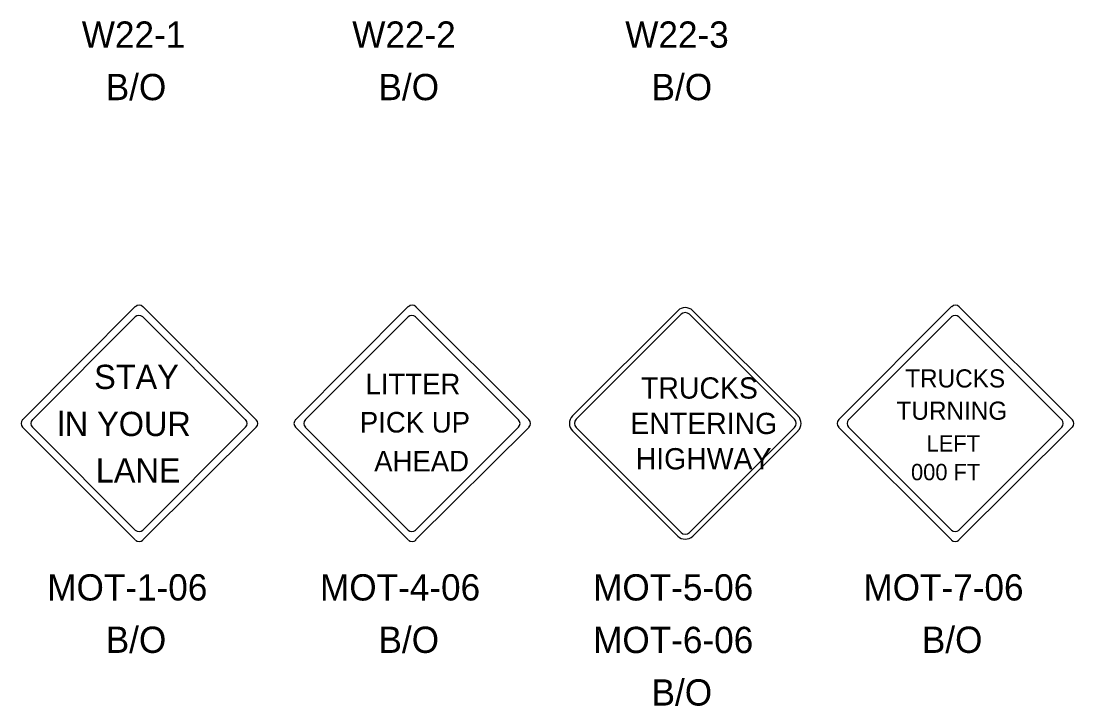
# Model space of a CAD drawing. Extents: x 10034 to 10794, y 10044 to 10499.
# Drawn here: x 10033.9 to 10174.1, y 10063.7 to 10155 of the extents above; entities that cross this region are included whole.
import ezdxf

# ---------------------------------------------------------------- set-up
doc = ezdxf.new("R2010")
doc.units = 0
for name, color, linetype in [('DSIndex', 7, 'Continuous'), ('DSSheetNo', 7, 'Continuous'), ('DSText', 7, 'Continuous'), ('DSTitle', 7, 'Continuous'), ('PlotBorder_dp', 7, 'Continuous')]:
    doc.layers.add(name, color=color, linetype=linetype)

msp = doc.modelspace()

# ---------------------------------------------------------------- linework, layer by layer
at = {"layer": 'DSSheetNo'}
for p, q in [((10049.13, 10116.94), (10034.1, 10101.87)), ((10065.24, 10101.87), (10050.12, 10116.94)), ((10085.48, 10116.94), (10070.46, 10101.87)), ((10101.59, 10101.87), (10086.47, 10116.94)), ((10157.83, 10116.94), (10142.81, 10101.87)), ((10173.94, 10101.87), (10158.82, 10116.94)), ((10034.1, 10100.87), (10049.13, 10085.85)), ((10050.12, 10085.85), (10065.23, 10100.86)), ((10070.46, 10100.87), (10085.48, 10085.85)), ((10086.47, 10085.85), (10101.59, 10100.87)), ((10142.81, 10100.87), (10157.83, 10085.85)), ((10158.82, 10085.85), (10173.93, 10100.86))]:
    msp.add_line(p, q, dxfattribs=at)
for centre, start, end in [((10049.66, 10116.41), 45, 135), ((10086.02, 10116.41), 45, 135), ((10158.37, 10116.41), 45, 135), ((10034.63, 10101.38), 135, 225), ((10064.74, 10101.37), 315, 45), ((10070.98, 10101.38), 135, 225), ((10101.05, 10101.38), 315, 45), ((10143.33, 10101.38), 135, 225), ((10173.44, 10101.37), 315, 45), ((10049.66, 10086.34), 225, 315), ((10086.02, 10086.34), 225, 315)]:
    msp.add_arc(centre, 0.709, start, end, dxfattribs=at)
at = {"layer": 'DSText'}
for p, q in [((10107.37, 10102.38), (10121.38, 10116.39)), ((10137.4, 10102.38), (10123.38, 10116.39)), ((10121.38, 10086.36), (10107.37, 10100.37)), ((10123.38, 10086.36), (10137.4, 10100.37))]:
    msp.add_line(p, q, dxfattribs=at)
for centre, radius, start, end in [((10122.38, 10115.39), 1.42, 45, 135), ((10108.37, 10101.38), 1.42, 135, 225), ((10136.39, 10101.38), 1.42, 315, 45), ((10122.38, 10087.37), 1.42, 225, 315), ((10158.33, 10086.3), 0.663, 225, 315)]:
    msp.add_arc(centre, radius, start, end, dxfattribs=at)
at = {"layer": 'DSTitle'}
for p, q in [((10049.13, 10115.57), (10035.43, 10101.87)), ((10063.82, 10101.87), (10050.12, 10115.57)), ((10085.48, 10115.57), (10071.78, 10101.87)), ((10100.18, 10101.87), (10086.47, 10115.57)), ((10107.85, 10101.94), (10121.82, 10115.91)), ((10122.94, 10115.91), (10136.92, 10101.94)), ((10157.83, 10115.57), (10144.13, 10101.87)), ((10172.53, 10101.87), (10158.82, 10115.57)), ((10035.43, 10100.87), (10049.13, 10087.17)), ((10050.12, 10087.17), (10063.82, 10100.87)), ((10071.78, 10100.87), (10085.48, 10087.17)), ((10086.47, 10087.17), (10100.18, 10100.87)), ((10121.82, 10086.84), (10107.85, 10100.82)), ((10136.92, 10100.82), (10122.94, 10086.84)), ((10144.13, 10100.87), (10157.83, 10087.17)), ((10158.82, 10087.17), (10172.53, 10100.87))]:
    msp.add_line(p, q, dxfattribs=at)
for centre, radius, start, end in [((10122.38, 10115.35), 0.793, 45, 135), ((10049.62, 10115.06), 0.709, 45, 135), ((10085.98, 10115.06), 0.709, 45, 135), ((10158.32, 10115.06), 0.709, 45, 135), ((10035.94, 10101.38), 0.709, 135, 225), ((10063.32, 10101.38), 0.709, 315, 45), ((10072.29, 10101.38), 0.709, 135, 225), ((10099.67, 10101.37), 0.709, 315, 45), ((10108.41, 10101.38), 0.793, 135, 225), ((10136.36, 10101.38), 0.793, 315, 45), ((10144.64, 10101.38), 0.709, 135, 225), ((10172.02, 10101.38), 0.709, 315, 45), ((10049.63, 10087.67), 0.709, 225, 315), ((10085.98, 10087.67), 0.709, 225, 315), ((10122.38, 10087.4), 0.793, 225, 315), ((10158.34, 10087.67), 0.709, 225, 315)]:
    msp.add_arc(centre, radius, start, end, dxfattribs=at)

# ---------------------------------------------------------------- texts
at = {"layer": 'DSIndex'}
for s, p in [('W22-1', (10042.01, 10151.43)), ('W22-2', (10078.03, 10151.43)), ('B/O', (10045.2, 10144.44)), ('B/O', (10081.53, 10144.44))]:
    msp.add_text(s, height=3.5, dxfattribs=at).set_placement(p)
at = {"layer": 'PlotBorder_dp'}
for s, height, p in [('W22-3', 3.5, (10114.39, 10151.43)), ('B/O', 3.5, (10117.9, 10144.44)), ('STAY ', 3.227, (10043.66, 10105.96)), ('LITTER', 2.743, (10079.79, 10105.25)), ('TRUCKS', 2.42, (10151.68, 10106.16)), ('TRUCKS', 2.831, (10116.49, 10104.68)), ('TURNING', 2.42, (10150.52, 10101.86)), ('lN YOUR', 3.228, (10038.78, 10099.69)), ('PICK UP', 2.743, (10079.04, 10100.16)), ('ENTERING', 2.831, (10115.07, 10099.96)), ('LEFT', 2.178, (10154.52, 10097.63)), ('HIGHWAY', 2.831, (10115.78, 10095.25)), ('LANE', 3.228, (10043.88, 10093.5)), ('AHEAD', 2.743, (10080.95, 10094.97)), ('000 FT', 2.178, (10152.45, 10093.8)), ('MOT-1-06', 3.5, (10037.41, 10077.78)), ('MOT-4-06', 3.5, (10073.74, 10077.78)), ('MOT-5-06', 3.5, (10110.11, 10077.78)), ('MOT-7-06', 3.5, (10146.11, 10077.78)), ('B/O', 3.5, (10045.2, 10070.8)), ('B/O', 3.5, (10081.53, 10070.8)), ('MOT-6-06', 3.5, (10110.11, 10070.78)), ('B/O', 3.5, (10153.9, 10070.8)), ('B/O', 3.5, (10117.9, 10063.78))]:
    msp.add_text(s, height=height, dxfattribs=at).set_placement(p)

doc.saveas('drawing.dxf')
